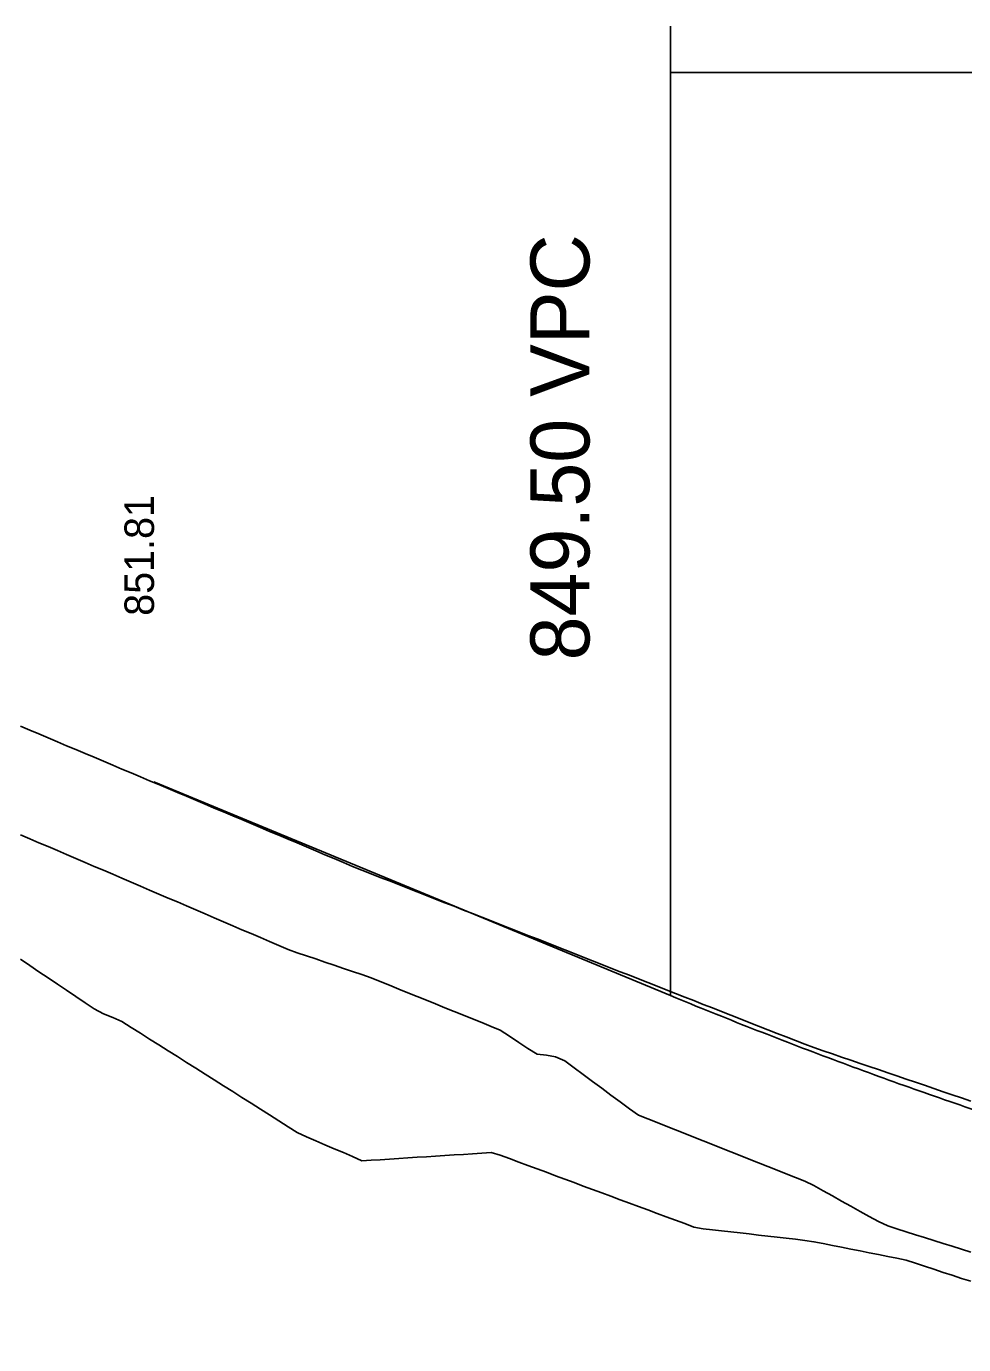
# Model space of a CAD drawing. Extents: x 1733669 to 1739080, y 1214897 to 1219897.
# Drawn here: x 1734950.9 to 1735052.5, y 1217853.9 to 1217996.7 of the extents above; entities that cross this region are included whole.
import ezdxf

# ---------------------------------------------------------------- set-up
doc = ezdxf.new("R2010")
doc.units = 0
for name, color, linetype in [('RD_DDB_Profile_EX', 7, 'Continuous'), ('RD_DDB_Profile_Lbl', 7, 'Continuous'), ('RD_DDB_Profile_PR', 7, 'Continuous'), ('RD_DDB_StripGrade', 7, 'Continuous'), ('RD_DDB_VCLbl', 7, 'Continuous'), ('RD_Sketch1', 7, 'Continuous'), ('RD_Sketch2', 7, 'Continuous')]:
    doc.layers.add(name, color=color, linetype=linetype)

msp = doc.modelspace()

# ---------------------------------------------------------------- linework, layer by layer
at = {"layer": 'RD_DDB_Profile_EX'}
for points in [[(1734950.3, 1217920.92), (1734951.3, 1217920.5), (1734952.3, 1217920.08), (1734953.3, 1217919.66), (1734954.3, 1217919.23), (1734955.3, 1217918.81), (1734956.3, 1217918.39), (1734957.3, 1217917.97), (1734958.3, 1217917.55), (1734959.3, 1217917.12), (1734960.3, 1217916.7), (1734961.3, 1217916.28), (1734962.3, 1217915.86), (1734963.3, 1217915.44), (1734964.3, 1217915.01), (1734965.3, 1217914.59), (1734966.3, 1217914.17), (1734967.3, 1217913.75), (1734968.3, 1217913.33), (1734969.3, 1217912.9), (1734970.3, 1217912.48), (1734971.3, 1217912.06), (1734972.3, 1217911.64), (1734973.3, 1217911.22), (1734974.3, 1217910.8), (1734975.3, 1217910.37), (1734976.3, 1217909.95), (1734977.3, 1217909.53), (1734978.3, 1217909.11), (1734979.3, 1217908.69), (1734980.3, 1217908.27), (1734981.3, 1217907.84), (1734982.3, 1217907.42), (1734983.3, 1217907)], [(1734983.3, 1217907), (1734984.3, 1217906.58), (1734985.3, 1217906.16), (1734986.3, 1217905.73), (1734987.3, 1217905.34), (1734988.3, 1217904.94), (1734989.3, 1217904.55), (1734990.3, 1217904.16), (1734991.3, 1217903.76), (1734992.3, 1217903.37), (1734993.3, 1217902.98), (1734994.3, 1217902.58), (1734995.3, 1217902.19), (1734996.3, 1217901.8), (1734997.3, 1217901.41), (1734998.3, 1217901.01), (1734999.3, 1217900.62), (1735000.3, 1217900.23), (1735001.3, 1217899.83), (1735002.3, 1217899.44), (1735003.3, 1217899.05), (1735004.3, 1217898.65), (1735005.3, 1217898.26), (1735006.3, 1217897.87), (1735007.3, 1217897.48), (1735008.3, 1217897.08), (1735009.3, 1217896.69), (1735010.3, 1217896.3), (1735011.3, 1217895.9), (1735012.3, 1217895.51), (1735013.3, 1217895.12), (1735014.3, 1217894.72), (1735015.3, 1217894.33), (1735016.3, 1217893.94), (1735017.3, 1217893.55), (1735018.3, 1217893.15), (1735019.3, 1217892.76), (1735020.3, 1217892.37), (1735021.3, 1217891.97), (1735022.3, 1217891.58), (1735023.3, 1217891.19), (1735024.3, 1217890.79), (1735025.3, 1217890.4), (1735026.3, 1217890.01), (1735027.3, 1217889.62), (1735028.3, 1217889.22), (1735029.3, 1217888.83), (1735030.3, 1217888.44), (1735031.3, 1217888.04), (1735032.3, 1217887.65), (1735033.3, 1217887.26), (1735034.3, 1217886.86), (1735035.3, 1217886.47), (1735036.3, 1217886.1), (1735037.3, 1217885.76), (1735038.3, 1217885.42), (1735039.3, 1217885.08), (1735040.3, 1217884.74), (1735041.3, 1217884.4), (1735042.3, 1217884.06), (1735043.3, 1217883.72), (1735044.3, 1217883.38), (1735045.3, 1217883.04), (1735046.3, 1217882.7), (1735047.3, 1217882.36), (1735048.3, 1217882.02), (1735049.3, 1217881.68), (1735050.3, 1217881.33), (1735051.3, 1217880.99), (1735052.3, 1217880.65), (1735053.3, 1217880.31)]]:
    msp.add_lwpolyline(points, dxfattribs=at)
at = {"layer": 'RD_DDB_Profile_PR'}
msp.add_line((1734964.77, 1217914.88), (1735020.77, 1217891.74), dxfattribs=at)
msp.add_spline([(1735020.77, 1217891.74), (1735025.17, 1217889.94), (1735029.57, 1217888.19), (1735033.97, 1217886.48), (1735038.37, 1217884.81), (1735042.77, 1217883.19), (1735047.17, 1217881.61), (1735051.57, 1217880.08), (1735055.97, 1217878.59), (1735060.37, 1217877.14), (1735064.77, 1217875.74), (1735069.17, 1217874.38), (1735073.57, 1217873.06), (1735077.97, 1217871.79), (1735082.37, 1217870.56), (1735086.77, 1217869.38), (1735091.17, 1217868.24), (1735095.57, 1217867.14), (1735099.97, 1217866.09), (1735104.37, 1217865.08), (1735108.77, 1217864.11), (1735113.17, 1217863.19), (1735117.57, 1217862.31), (1735121.97, 1217861.48), (1735126.37, 1217860.69), (1735130.77, 1217859.94), (1735135.17, 1217859.24), (1735139.57, 1217858.58), (1735143.97, 1217857.96), (1735148.37, 1217857.39), (1735152.77, 1217856.86), (1735157.17, 1217856.38), (1735161.57, 1217855.94), (1735165.97, 1217855.54), (1735170.37, 1217855.19), (1735174.77, 1217854.88), (1735179.17, 1217854.61), (1735183.57, 1217854.39), (1735187.97, 1217854.21), (1735192.37, 1217854.08), (1735196.77, 1217853.98), (1735201.17, 1217853.94), (1735205.57, 1217853.93), (1735209.97, 1217853.97), (1735214.37, 1217854.06), (1735218.77, 1217854.19), (1735223.17, 1217854.36), (1735227.57, 1217854.57), (1735231.97, 1217854.83), (1735236.37, 1217855.13), (1735240.77, 1217855.48)], degree=3, dxfattribs=at)
at = {"layer": 'RD_DDB_VCLbl'}
for p, q in [((1735020.77, 1217996.74), (1735020.77, 1217891.74)), ((1735020.77, 1217991.74), (1735240.77, 1217991.74))]:
    msp.add_line(p, q, dxfattribs=at)
at = {"layer": 'RD_Sketch1'}
for points in [[(1734950.3, 1217895.68), (1734951.3, 1217895.01), (1734952.3, 1217894.33), (1734953.3, 1217893.66), (1734954.3, 1217892.99), (1734955.3, 1217892.31), (1734956.3, 1217891.64), (1734957.3, 1217890.97), (1734958.3, 1217890.29), (1734959.3, 1217889.77), (1734960.3, 1217889.35), (1734961.3, 1217888.92), (1734962.3, 1217888.3), (1734963.3, 1217887.67), (1734964.3, 1217887.03), (1734965.3, 1217886.4), (1734966.3, 1217885.77), (1734967.3, 1217885.14), (1734968.3, 1217884.5), (1734969.3, 1217883.87), (1734970.3, 1217883.24), (1734971.3, 1217882.61), (1734972.3, 1217881.97), (1734973.3, 1217881.34), (1734974.3, 1217880.71), (1734975.3, 1217880.08), (1734976.3, 1217879.44), (1734977.3, 1217878.81), (1734978.3, 1217878.18), (1734979.3, 1217877.54), (1734980.3, 1217876.91), (1734981.3, 1217876.43), (1734982.3, 1217876), (1734983.3, 1217875.58)], [(1734983.3, 1217875.58), (1734984.3, 1217875.15), (1734985.3, 1217874.73), (1734986.3, 1217874.3), (1734987.3, 1217873.83), (1734988.3, 1217873.9), (1734989.3, 1217873.96), (1734990.3, 1217874.03), (1734991.3, 1217874.09), (1734992.3, 1217874.16), (1734993.3, 1217874.22), (1734994.3, 1217874.29), (1734995.3, 1217874.35), (1734996.3, 1217874.41), (1734997.3, 1217874.48), (1734998.3, 1217874.54), (1734999.3, 1217874.61), (1735000.3, 1217874.67), (1735001.3, 1217874.74), (1735002.3, 1217874.45), (1735003.3, 1217874.08), (1735004.3, 1217873.71), (1735005.3, 1217873.34), (1735006.3, 1217872.97), (1735007.3, 1217872.6), (1735008.3, 1217872.23), (1735009.3, 1217871.85), (1735010.3, 1217871.48), (1735011.3, 1217871.11), (1735012.3, 1217870.74), (1735013.3, 1217870.37), (1735014.3, 1217870), (1735015.3, 1217869.63), (1735016.3, 1217869.26), (1735017.3, 1217868.89), (1735018.3, 1217868.52), (1735019.3, 1217868.15), (1735020.3, 1217867.78), (1735021.3, 1217867.41), (1735022.3, 1217867.04), (1735023.3, 1217866.67), (1735024.3, 1217866.49), (1735025.3, 1217866.38), (1735026.3, 1217866.26), (1735027.3, 1217866.15), (1735028.3, 1217866.03), (1735029.3, 1217865.92), (1735030.3, 1217865.8), (1735031.3, 1217865.68), (1735032.3, 1217865.57), (1735033.3, 1217865.45), (1735034.3, 1217865.34), (1735035.3, 1217865.22), (1735036.3, 1217865.07), (1735037.3, 1217864.87), (1735038.3, 1217864.67), (1735039.3, 1217864.47), (1735040.3, 1217864.28), (1735041.3, 1217864.08), (1735042.3, 1217863.88), (1735043.3, 1217863.69), (1735044.3, 1217863.49), (1735045.3, 1217863.29), (1735046.3, 1217863.07), (1735047.3, 1217862.74), (1735048.3, 1217862.42), (1735049.3, 1217862.09), (1735050.3, 1217861.76), (1735051.3, 1217861.44), (1735052.3, 1217861.11), (1735053.3, 1217860.79)]]:
    msp.add_lwpolyline(points, dxfattribs=at)
at = {"layer": 'RD_Sketch2'}
for points in [[(1734950.3, 1217909.15), (1734951.3, 1217908.73), (1734952.3, 1217908.3), (1734953.3, 1217907.88), (1734954.3, 1217907.45), (1734955.3, 1217907.02), (1734956.3, 1217906.6), (1734957.3, 1217906.17), (1734958.3, 1217905.74), (1734959.3, 1217905.31), (1734960.3, 1217904.88), (1734961.3, 1217904.45), (1734962.3, 1217904.02), (1734963.3, 1217903.59), (1734964.3, 1217903.16), (1734965.3, 1217902.74), (1734966.3, 1217902.31), (1734967.3, 1217901.88), (1734968.3, 1217901.45), (1734969.3, 1217901.02), (1734970.3, 1217900.59), (1734971.3, 1217900.16), (1734972.3, 1217899.73), (1734973.3, 1217899.3), (1734974.3, 1217898.87), (1734975.3, 1217898.45), (1734976.3, 1217898.02), (1734977.3, 1217897.59), (1734978.3, 1217897.17), (1734979.3, 1217896.74), (1734980.3, 1217896.38), (1734981.3, 1217896.05), (1734982.3, 1217895.71), (1734983.3, 1217895.37)], [(1734983.3, 1217895.37), (1734984.3, 1217895.03), (1734985.3, 1217894.69), (1734986.3, 1217894.35), (1734987.3, 1217894.01), (1734988.3, 1217893.67), (1734989.3, 1217893.26), (1734990.3, 1217892.86), (1734991.3, 1217892.45), (1734992.3, 1217892.05), (1734993.3, 1217891.64), (1734994.3, 1217891.24), (1734995.3, 1217890.83), (1734996.3, 1217890.43), (1734997.3, 1217890.02), (1734998.3, 1217889.62), (1734999.3, 1217889.21), (1735000.3, 1217888.81), (1735001.3, 1217888.4), (1735002.3, 1217887.99), (1735003.3, 1217887.33), (1735004.3, 1217886.67), (1735005.3, 1217886.01), (1735006.3, 1217885.41), (1735007.3, 1217885.27), (1735008.3, 1217885.12), (1735009.3, 1217884.66), (1735010.3, 1217883.92), (1735011.3, 1217883.18), (1735012.3, 1217882.44), (1735013.3, 1217881.7), (1735014.3, 1217880.96), (1735015.3, 1217880.22), (1735016.3, 1217879.48), (1735017.3, 1217878.78), (1735018.3, 1217878.38), (1735019.3, 1217877.99), (1735020.3, 1217877.59), (1735021.3, 1217877.19), (1735022.3, 1217876.79), (1735023.3, 1217876.4), (1735024.3, 1217876), (1735025.3, 1217875.6), (1735026.3, 1217875.21), (1735027.3, 1217874.81), (1735028.3, 1217874.41), (1735029.3, 1217874.01), (1735030.3, 1217873.62), (1735031.3, 1217873.22), (1735032.3, 1217872.82), (1735033.3, 1217872.43), (1735034.3, 1217872.03), (1735035.3, 1217871.63), (1735036.3, 1217871.16), (1735037.3, 1217870.6), (1735038.3, 1217870.04), (1735039.3, 1217869.48), (1735040.3, 1217868.92), (1735041.3, 1217868.36), (1735042.3, 1217867.81), (1735043.3, 1217867.25), (1735044.3, 1217866.79), (1735045.3, 1217866.47), (1735046.3, 1217866.15), (1735047.3, 1217865.84), (1735048.3, 1217865.52), (1735049.3, 1217865.21), (1735050.3, 1217864.89), (1735051.3, 1217864.58), (1735052.3, 1217864.26), (1735053.3, 1217863.95)]]:
    msp.add_lwpolyline(points, dxfattribs=at)

# ---------------------------------------------------------------- texts
at = {"layer": 'RD_DDB_Profile_Lbl'}
msp.add_text('851.81', height=3.2, rotation=90, dxfattribs=at).set_placement((1734964.77, 1217932.88))
at = {"layer": 'RD_DDB_StripGrade'}
msp.add_text('849.50 VPC', height=6.4, rotation=90, dxfattribs=at).set_placement((1735011.97, 1217928.05))

doc.saveas('drawing.dxf')
